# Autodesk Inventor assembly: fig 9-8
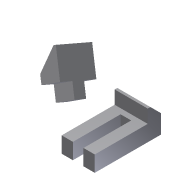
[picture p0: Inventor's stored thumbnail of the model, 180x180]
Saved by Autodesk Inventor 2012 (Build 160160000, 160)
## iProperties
Shininess: 64.0
Length Units: 11269
Angle Units: 11279
Time Units: 11290
Mass Units: 11283
Length Display Precision: 3
Angle Display Precision: 2
Created: 2002-01
Part Number: fig 9-8
Document SubType Name: Assembly
Designer: ***
Density: 0.0
Volumn: 0.0
Area: 0.0
PropertySet Name: Model Information
Control State: 0
Master: False
Checked Out: False
Author: ***
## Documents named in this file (3)
- C:\Users\CadCim\Documents\SAILESH\inventor-2011-fact-prt\c09_inv_2011-prt\c09_inv_2012_prt\fig 9-8.iam
- C:\Users\CadCim\Documents\SAILESH\inventor-2011-fact-prt\c09_inv_2011-prt\c09_inv_2012_prt\Part3.ipt
- C:\Users\CadCim\Documents\SAILESH\inventor-2011-fact-prt\c09_inv_2011-prt\c09_inv_2012_prt\Part4.ipt
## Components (2 placed, 2 different names)
1. Part3:1
2. Part4:1
